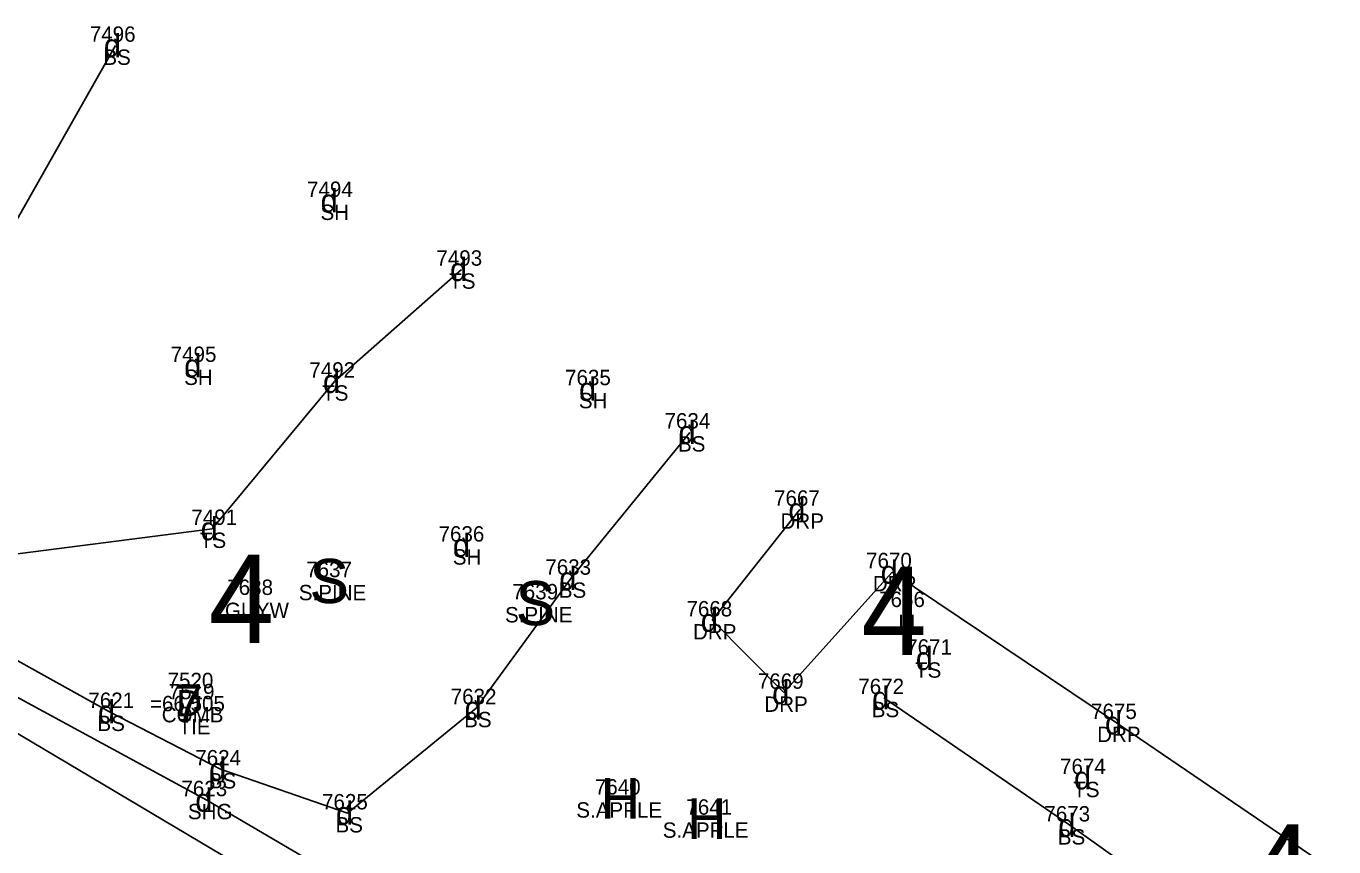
# Model space of a CAD drawing. Extents: x 69415 to 80913, y 7576 to 15059.
# Drawn here: x 76268.3 to 76438.3, y 14138 to 14244.7 of the extents above; entities that cross this region are included whole.
import ezdxf

# ---------------------------------------------------------------- set-up
doc = ezdxf.new("R2010")
doc.units = 0
for name, color, linetype in [('Level 1', 7, 'Continuous'), ('Level 11', 7, 'Continuous'), ('Level 14', 7, 'Continuous'), ('Level 15', 7, 'Continuous'), ('Level 46', 7, 'Continuous'), ('Level 47', 7, 'Continuous'), ('Level 48', 7, 'Continuous')]:
    doc.layers.add(name, color=color, linetype=linetype)

msp = doc.modelspace()

# ---------------------------------------------------------------- linework, layer by layer
at = {"layer": 'Level 11'}
for p, q in [((76368.92, 14181.83), (76357.54, 14167.44)), ((76366.82, 14158.03), (76380.92, 14173.71)), ((76380.92, 14173.71), (76410.09, 14154.1)), ((76247.19, 14168.22), (76291.82, 14144.07)), ((76357.54, 14167.44), (76366.82, 14158.03)), ((76251.05, 14162.32), (76304.15, 14130.78)), ((76410.09, 14154.1), (76438.35, 14134.88)), ((76291.82, 14144.07), (76307.02, 14135.12))]:
    msp.add_line(p, q, dxfattribs=at)
at = {"layer": 'Level 48'}
for p, q in [((76279.93, 14242.15), (76262.77, 14211.84)), ((76308.41, 14198.49), (76324.93, 14213.04)), ((76292.51, 14179.34), (76308.41, 14198.49)), ((76339.14, 14172.86), (76354.64, 14191.87)), ((76259.73, 14175.13), (76292.51, 14179.34)), ((76245.26, 14174.39), (76279.16, 14155.54)), ((76326.84, 14156.03), (76339.14, 14172.86)), ((76379.82, 14157.34), (76404.02, 14140.78)), ((76310.11, 14142.35), (76326.84, 14156.03)), ((76279.16, 14155.54), (76293.62, 14148.07)), ((76293.62, 14148.07), (76310.11, 14142.35)), ((76404.02, 14140.78), (76424.47, 14126.31))]:
    msp.add_line(p, q, dxfattribs=at)

# ---------------------------------------------------------------- texts
at = {"layer": 'Level 1'}
msp.add_text('7', height=5, dxfattribs=at).set_placement((76287.57, 14154.11))
at = {"layer": 'Level 14'}
for s, height, p in [('S', 5.75, (76305.17, 14169.67)), ('S', 5.75, (76331.98, 14166.79)), ('H', 5.3, (76343.02, 14141.63)), ('H', 5.3, (76354.26, 14139.01))]:
    msp.add_text(s, height=height, dxfattribs=at).set_placement(p)
at = {"layer": 'Level 15'}
for s, height, p in [('4', 11.5, (76292.04, 14164.48)), ('4', 11.5, (76376.89, 14162.91)), ('D', 3.4, (76287.87, 14154.97)), ('4', 11.5, (76427.1, 14129.43))]:
    msp.add_text(s, height=height, dxfattribs=at).set_placement(p)
at = {"layer": 'Level 46'}
for s, p in [('7496', (76276.61, 14242.65)), ('BS', (76278.37, 14239.65)), ('7494', (76304.85, 14222.48)), ('SH', (76306.6, 14219.48)), ('7493', (76321.67, 14213.54)), ('TS', (76323.34, 14210.54)), ('7495', (76287.12, 14201.03)), ('SH', (76288.87, 14198.03)), ('7492', (76305.15, 14198.99)), ('7635', (76338.4, 14198)), ('TS', (76306.82, 14195.99)), ('SH', (76340.19, 14195)), ('7634', (76351.33, 14192.37)), ('BS', (76353.08, 14189.37)), ('7667', (76365.57, 14182.33)), ('7491', (76289.81, 14179.84)), ('DRP', (76366.41, 14179.33)), ('7636', (76321.95, 14177.67)), ('TS', (76290.92, 14176.84)), ('SH', (76323.8, 14174.67)), ('7670', (76377.53, 14174.21)), ('7637', (76304.74, 14173.04)), ('7633', (76335.83, 14173.36)), ('7638', (76294.48, 14170.73)), ('DRP', (76378.41, 14171.21)), ('S.PINE', (76303.78, 14170.04)), ('7639', (76331.54, 14170.16)), ('BS', (76337.58, 14170.36)), ('7666', (76379.23, 14169.16)), ('GUYW', (76294.18, 14167.73)), ('S.PINE', (76330.59, 14167.16)), ('7668', (76354.18, 14167.94)), ('LI', (76381.74, 14166.16)), ('DRP', (76355.03, 14164.94)), ('7671', (76382.75, 14162.97)), ('TS', (76383.9, 14159.97)), ('7520', (76286.72, 14158.61)), ('7519', (76286.87, 14157.17)), ('7669', (76363.46, 14158.53)), ('7672', (76376.52, 14157.84)), ('7621', (76276.42, 14156.04)), ('=66.505', (76284.43, 14155.61)), ('7632', (76323.53, 14156.53)), ('DRP', (76364.31, 14155.53)), ('COMB', (76285.96, 14154.17)), ('BS', (76378.27, 14154.84)), ('7675', (76406.78, 14154.6)), ('BS', (76277.6, 14153.04)), ('TIE', (76288.15, 14152.61)), ('BS', (76325.28, 14153.53)), ('DRP', (76407.58, 14151.6)), ('7624', (76290.32, 14148.57)), ('7674', (76402.75, 14147.44)), ('BS', (76292.07, 14145.57)), ('7623', (76288.52, 14144.57)), ('7640', (76342.27, 14144.78)), ('TS', (76404.47, 14144.44)), ('7625', (76306.8, 14142.85)), ('S.APPLE', (76339.86, 14141.78)), ('7641', (76354.17, 14142.16)), ('SHG', (76289.36, 14141.57)), ('7673', (76400.71, 14141.28)), ('BS', (76308.55, 14139.85)), ('S.APPLE', (76351.1, 14139.16)), ('BS', (76402.46, 14138.28))]:
    msp.add_text(s, height=2, dxfattribs=at).set_placement(p)
at = {"layer": 'Level 47'}
for p in [(76278.43, 14240.65), (76306.61, 14220.48), (76323.43, 14211.54), (76288.88, 14199.03), (76306.91, 14196.99), (76340.21, 14196), (76353.14, 14190.37), (76367.42, 14180.33), (76291.01, 14177.84), (76323.81, 14175.67), (76337.64, 14171.36), (76379.42, 14172.21), (76356.04, 14165.94), (76383.99, 14160.97), (76365.32, 14156.53), (76378.32, 14155.84), (76325.34, 14154.53), (76277.66, 14154.04), (76408.59, 14152.6), (76292.12, 14146.57), (76404.56, 14145.44), (76290.32, 14142.57), (76308.61, 14140.85), (76402.52, 14139.28)]:
    msp.add_text('d', height=3, dxfattribs=at).set_placement(p)

doc.saveas('drawing.dxf')
